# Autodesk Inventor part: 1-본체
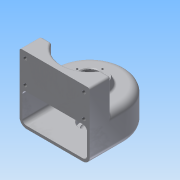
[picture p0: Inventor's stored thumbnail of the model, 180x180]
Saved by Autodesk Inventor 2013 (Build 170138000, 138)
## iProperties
Created: 2015-02
Part Number: 1-본체
Material: 알루미늄 6061
Document SubType Name: Modeling
Designer: Administrator
Density: 2.71 g/cm^3
Mass: 575.525 g
Surface Area: 708.306 cm^2
Volume: 212.371 cm^3
Author: Administrator
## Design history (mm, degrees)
sketch "스케치1"
  geometry: L1 (-50, 0)-(-50, -50); L2 (50, 0)-(50, -50); L3 (-50, -50)-(50, -50); A1 r 50 centre (0, 0) between (50, 0) and (-50, 0); 1 further point
  constraints: 6 end point, 2 parallel, 2 point on circle, 2 tangent, 1 centre point, 1 coincident, 1 perpendicular, 1 vertical
  dimensions: "d0" = 50 radius of A1; "d2" = 50 distance of L2.start L2.end
extrude "돌출1" new body sketch "스케치1" stored distance "d3" = 50; taper "d4" = 0 deg
sketch "스케치2"
  geometry: L1 (-50, 0)-(-50, -50) reference; L2 (-50, -50)-(50, -50) reference; L3 (50, -50)-(50, 0) reference; L4 (-50, -20)-(-50, -50); L5 (50, -20)-(50, -50); L6 (-50, -50)-(50, -50); L7 (-50, -20)-(-34.641, -20); L8 (34.641, -20)-(50, -20); A1 r 50 centre (0, 0) between (50, 0) and (-50, 0) reference; A2 r 40 centre (0, 0) between (-34.641, -20) and (34.641, -20)
  constraints: 10 end point, 3 perpendicular, 3 point on line, 2 point on circle, 1 centre point, 1 coincident, 1 collinear
  dimensions: "d5" = 40 radius of A2; "d7" = 30 distance of L4.start L1.end; "d8" = 30 distance of L5.start L5.end
extrude "돌출2" join sketch "스케치2" distance "d9" = 45; taper "d10" = 0 deg
node "작업 평면1"
sketch "스케치3"
  geometry: L1 (-50, 0)-(-50, -20) reference; L2 (50, -20)-(50, 0) reference; L3 (-50, -20)-(-50, -50) reference; L4 (50, -50)-(50, -20) reference; L5 (-46, -50)-(-46, -20); L6 (-46, -20)-(-46, 0); L7 (46, 0)-(46, -20); L8 (46, -20)-(46, -50); L9 (-46, -50)-(46, -50); L10 (-50, -50)-(50, -50) reference; A1 r 50 centre (0, 0) between (50, 0) and (-50, 0) reference; A2 r 46 centre (0, 0) between (46, 0) and (-46, 0); 1 further point
  constraints: 10 end point, 2 point on circle, 1 centre point, 1 collinear, 1 perpendicular, 4 other
  dimensions: "d12" = 4 radial gap between concentric circles of A1 A2
extrude "돌출3" cut sketch "스케치3" stored distance "d13" = 42; taper "d14" = 0 deg
sketch "스케치4"
  geometry: C1 r 25 at (0, 0); A1 r 50 centre (0, 0) between (50, 0) and (-50, 0) reference; A2 r 40 centre (0, 0) between (-34.641, -20) and (34.641, -20) reference
  constraints: 2 coincident, 1 centre point
  dimensions: "d15" = 50 diameter of C1
extrude "돌출4" join sketch "스케치4" distance "d17" = 10; taper "d18" = -20 deg
sketch "스케치5"
  geometry: C1 r 20 at (0, 0); A1 r 50 centre (0, 0) between (50, 0) and (-50, 0) reference
  constraints: 1 centre point, 1 coincident
  dimensions: "d19" = 40 diameter of C1
extrude "돌출5" join sketch "스케치5" distance "d21" = 9; taper "d22" = 0 deg
hole "구멍1" diameter "d25" = 20; stored, may be unused: countersink angle "d29" = 90 deg, drill point angle "d31" = 0 deg; dims "d23" = 10, "d24" = 10, "d26" = 6, "d27" = 28, "d28" = 10, "d30" = 14
sketch "스케치6"
  geometry: A1 r 46 centre (0, 0) between (46, 0) and (-46, 0) reference; 1 further point
  constraints: 1 coincident
hole "구멍2" sketch "스케치6" at (0, 0) diameter "d34" = 20; stored, may be unused: countersink angle "d38" = 90 deg, drill point angle "d40" = 0 deg; dims "d35" = 6, "d36" = 28, "d37" = 8, "d39" = 10
node "작업 평면2"
sketch "스케치7"
  geometry: L1 (-50, -25)-(50, -25) reference; 2 further points
  constraints: 1 coincident, 1 other
  dimensions: "d41" = 25 distance from line of point (0, 0) L1
feature "엠보싱1" sketch "스케치7" dims "d0" = 50, "d2" = 50, "d42" = 0.5, "d43" = 0
fillet "모깎기1" dims "d44" = 10, "d45" = 3
fillet "모깎기2" dims "d46" = 0.3, "d47" = 3, "d78" = 6
sketch "스케치8"
  geometry: C1 r 14 at (0, 0) reference; C2 r 21.36 at (0, 0) reference; A1 r 18 centre (0, 0) between (0, 18) and (-18, 0); 2 further points
  constraints: 4 point on circle, 2 horizontal alignment, 2 vertical alignment, 1 centre point, 1 coincident
  dimensions: "d48" = 36 diameter of A1
hole "구멍3" sketch "스케치8" at (0, 18), (-18, 0), (0, -18), (18, 0) diameter "d50" = 2.459; stored, may be unused: countersink angle "d54" = 90 deg, drill point angle "d56" = 118 deg; dims "d51" = 6, "d52" = 28, "d53" = 8, "d55" = 9
sketch "스케치11"
  geometry: L1 (97, -3)-(97, -85) reference; L2 (0, 0)-(94, 0) reference; L3 (88.75, -9)-(5.25, -9); L4 (5.25, -9)-(5.25, -42); L5 (5.25, -42)-(88.75, -42); L6 (88.75, -42)-(88.75, -9); 5 further points
  constraints: 8 end point, 4 coincident, 2 parallel, 1 horizontal, 1 perpendicular
  dimensions: "d66" = 33 distance of L5.end L3.start; "d68" = 83.5 distance of L3.start L3.end; "d69" = 9 distance between parallel lines of L2 L3; "d70" = 8.25 distance between parallel lines of L6 L1
hole "구멍4" sketch "스케치11" at (88.75, -9), (88.75, -42), (5.25, -9), (5.25, -42) diameter "d71" = 5.134; stored, may be unused: countersink angle "d75" = 90 deg, drill point angle "d77" = 118 deg; dims "d72" = 10, "d73" = 28, "d74" = 8, "d76" = 13
chamfer "모따기1" distance "d79" = 1; stored, may be unused: second distance "d80" = 2, angle "d81" = 45 deg
node "솔리드1"
other parameters: "d11" = 0
